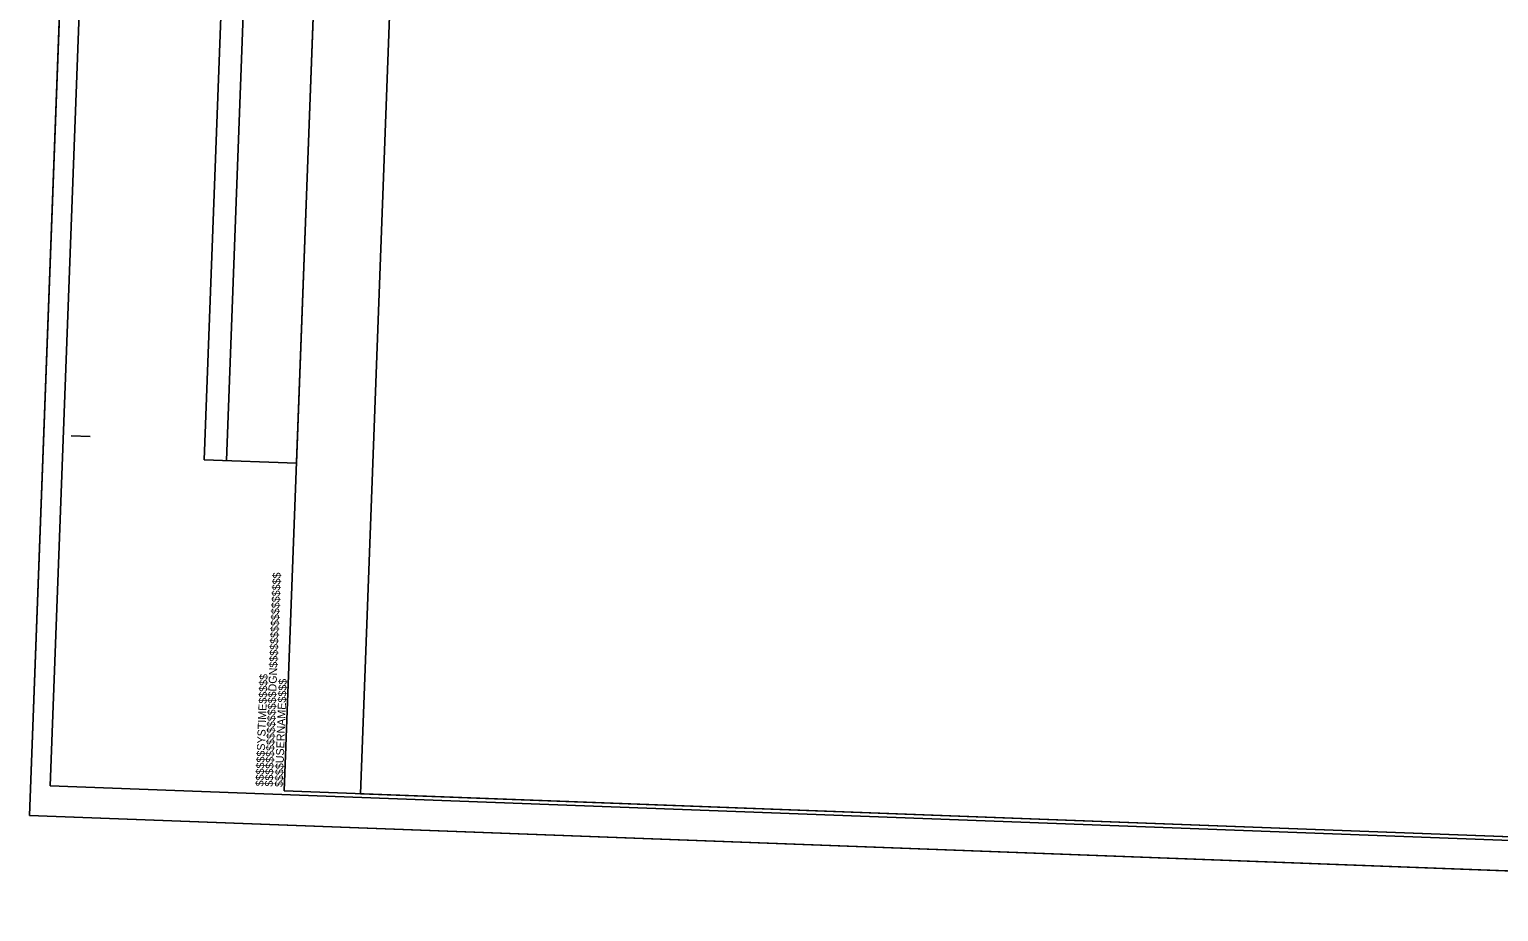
# Model space of a CAD drawing. Extents: x 2170073 to 2172001, y 723518 to 724675.
# Drawn here: x 2170073 to 2171037, y 723518 to 724097 of the extents above; entities that cross this region are included whole.
import ezdxf

# ---------------------------------------------------------------- set-up
doc = ezdxf.new("R2010")
doc.units = 0
for name, color, linetype in [('Sheet Block Revision CELL', 7, 'Continuous'), ('Sheet Clip Boundary CELL', 7, 'Continuous'), ('Sheet Cutting Line CELL', 7, 'Continuous'), ('Sheet Plan CELL', 7, 'Continuous'), ('Sheet Plan Layout CELL', 7, 'Continuous'), ('Sheet Plot Border Inside CELL', 7, 'Continuous'), ('Sheet Plot Border Outside CELL', 7, 'Continuous')]:
    doc.layers.add(name, color=color, linetype=linetype)

msp = doc.modelspace()

# ---------------------------------------------------------------- linework, layer by layer
at = {"layer": 'Sheet Block Revision CELL'}
msp.add_line((2170202.2, 723813.97), (2170231.75, 724604.06), dxfattribs=at)
msp.add_lwpolyline([(2170187.66, 723814.49), (2170217.22, 724604.59), (2170277.72, 724602.35), (2170248.16, 723812.25)], close=True, dxfattribs=at)
at = {"layer": 'Sheet Clip Boundary CELL'}
msp.add_lwpolyline([(2170290.07, 723595.53), (2171689.11, 723543.19), (2171720.45, 724381.12), (2171531.32, 724388.19), (2171539.23, 724599.53), (2170329.33, 724644.8)], close=True, dxfattribs=at)
at = {"layer": 'Sheet Cutting Line CELL'}
for p, q in [((2170113.83, 724675.36), (2170072.89, 723581.13)), ((2170072.89, 723581.13), (2171755.22, 723518.19))]:
    msp.add_line(p, q, dxfattribs=at)
at = {"layer": 'Sheet Plan CELL'}
for p, q in [((2170100.24, 723830.28), (2170112.73, 723829.8)), ((2170240.11, 723597.4), (2170240.11, 723597.4))]:
    msp.add_line(p, q, dxfattribs=at)
for points in [[(2171778.35, 724590.59), (2170279.36, 724646.67), (2170240.11, 723597.4), (2171739.07, 723541.32)], [(2170240.11, 723597.4), (2170279.34, 724646.64), (2171578.42, 724598.08), (2171572.82, 724448.12), (2171772.72, 724440.63), (2171739.07, 723541.32)]]:
    msp.add_lwpolyline(points, close=True, dxfattribs=at)
at = {"layer": 'Sheet Plan Layout CELL'}
msp.add_lwpolyline([(2170279.34, 724646.64), (2170240.11, 723597.4), (2171739.06, 723541.32), (2171770.41, 724379.25), (2171531.32, 724388.19), (2171539.23, 724599.53)], close=True, dxfattribs=at)
at = {"layer": 'Sheet Plot Border Inside CELL'}
msp.add_lwpolyline([(2170086.63, 723600.63), (2171751.46, 723538.36), (2171790.91, 724592.61), (2170126.08, 724654.89)], close=True, dxfattribs=at)
at = {"layer": 'Sheet Plot Border Outside CELL'}
msp.add_lwpolyline([(2170072.89, 723581.13), (2171755.22, 723518.19), (2171796.16, 724612.42), (2170113.83, 724675.36)], close=True, dxfattribs=at)

# ---------------------------------------------------------------- texts
at = {"layer": 'Sheet Plan CELL'}
for s, p in [('$$$$$$$$$$$$$$$$DGN$$$$$$$$$$$$$$$$', (2170232.56, 723600.05)), ('$$$$$$SYSTIME$$$$$', (2170226.49, 723600.25)), ('$$$$USERNAME$$$$', (2170239.11, 723599.82))]:
    msp.add_text(s, height=5.25, rotation=87.85741, dxfattribs=at).set_placement(p)

doc.saveas('drawing.dxf')
